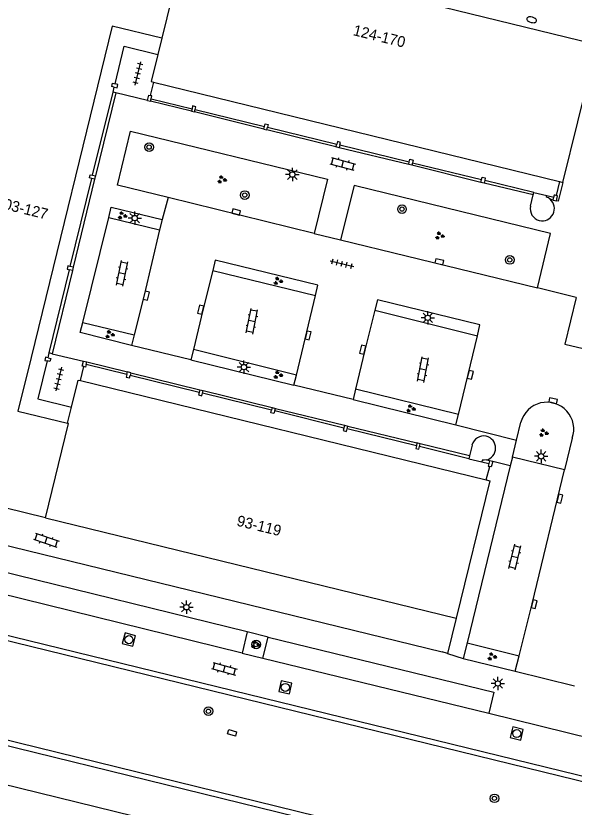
# Model space of a CAD drawing. Extents: x 125000 to 129004, y 397500 to 399008.
# Drawn here: x 126192.5 to 126244.2, y 398305.6 to 398378.8 of the extents above; entities that cross this region are included whole.
import ezdxf

# ---------------------------------------------------------------- set-up
doc = ezdxf.new("R2010")
doc.units = 0
for name, color, linetype in [('gg-afsc-hekwerk', 7, 'Continuous'), ('gg-anno-huisnummerreeks BGT', 7, 'Continuous'), ('gg-bbg-hoofdgebouw', 7, 'Continuous'), ('gg-bbg-onder overbouw', 7, 'Continuous'), ('gg-bbg-pand overbouw', 7, 'Continuous'), ('gg-bbg-pilaar onder overbouw', 7, 'Continuous'), ('gg-bbg-pilaar pand', 7, 'Continuous'), ('gg-bbg-toegangstrap', 7, 'Continuous'), ('gg-bbg-tussenscheiding', 7, 'Continuous'), ('gg-knt-verharding', 7, 'Continuous'), ('gg-knt-verharding nz', 7, 'Continuous'), ('gt-grn-weggrens', 7, 'Continuous'), ('gt-symb-boom', 7, 'Continuous'), ('gt-symb-brandkraan', 7, 'Continuous'), ('gt-symb-groenvak', 7, 'Continuous'), ('gt-symb-klinker verharding', 7, 'Continuous'), ('gt-symb-kolk', 7, 'Continuous'), ('gt-symb-kolk center center', 7, 'Continuous'), ('gt-symb-lichtmast', 7, 'Continuous'), ('gt-symb-rioolschacht', 7, 'Continuous'), ('gt-symb-tegel verharding', 7, 'Continuous')]:
    doc.layers.add(name, color=color, linetype=linetype)

# ---------------------------------------------------------------- blocks, each defined once
blk = doc.blocks.new('gt0-GRVAK')
at = {"layer": 'gt-symb-groenvak'}
for p, q in [((-0.11, 0.189), (-0.228, 0.24)), ((-0.182, 0.153), (0.088, 0.153)), ((-0.091, 0.211), (-0.156, 0.322)), ((-0.047, 0.214), (-0.047, 0.393)), ((-0.004, 0.211), (0.061, 0.322)), ((0.015, 0.189), (0.133, 0.24)), ((0.262, -0.052), (0.197, 0.059)), ((0.305, -0.049), (0.305, 0.13)), ((0.349, -0.052), (0.414, 0.059)), ((-0.245, -0.228), (-0.363, -0.177)), ((-0.318, -0.264), (-0.047, -0.264)), ((-0.226, -0.206), (-0.291, -0.095)), ((-0.183, -0.203), (-0.183, -0.024)), ((-0.139, -0.206), (-0.074, -0.095)), ((-0.12, -0.228), (-0.002, -0.177)), ((0.243, -0.074), (0.125, -0.023)), ((0.17, -0.11), (0.441, -0.11)), ((0.368, -0.074), (0.486, -0.023))]:
    blk.add_line(p, q, dxfattribs=at)
blk = doc.blocks.new('gt0-BOOM')
at = {"layer": 'gt-symb-boom'}
for radius in [0.4, 0.2]:
    blk.add_circle((0, 0), radius, dxfattribs=at)
blk = doc.blocks.new('gt0-TEG1')
at = {"layer": 'gt-symb-tegel verharding'}
for p, q in [((-1.125, 0), (1.125, 0)), ((-0.9, -0.25), (-0.9, 0.25)), ((-0.45, -0.25), (-0.45, 0.25)), ((0, -0.25), (0, 0.25)), ((0.45, -0.25), (0.45, 0.25)), ((0.9, -0.25), (0.9, 0.25))]:
    blk.add_line(p, q, dxfattribs=at)
blk = doc.blocks.new('gt0-KOLK')
at = {"layer": 'gt-symb-kolk'}
blk.add_lwpolyline([(0, 0), (0.375, 0), (0.375, 0.4), (-0.375, 0.4), (-0.375, 0), (0, 0)], dxfattribs=at)
blk = doc.blocks.new('gt0-KL1')
at = {"layer": 'gt-symb-klinker verharding'}
for p, q in [((-1.15, 0.3), (1.15, 0.3)), ((-1, -0.3), (-1, 0.3)), ((-0.5, 0.3), (-0.5, 0.45)), ((0, -0.3), (0, 0.3)), ((0.5, 0.3), (0.5, 0.45)), ((1, -0.3), (1, 0.3)), ((-1.15, -0.3), (1.15, -0.3)), ((-0.5, -0.45), (-0.5, -0.3)), ((0.5, -0.45), (0.5, -0.3))]:
    blk.add_line(p, q, dxfattribs=at)
blk = doc.blocks.new('gt0-LMAST')
at = {"layer": 'gt-symb-lichtmast'}
for p, q in [((-0.182, 0.173), (-0.447, 0.438)), ((-0.005, 0.246), (-0.005, 0.621)), ((0.172, 0.173), (0.437, 0.438)), ((-0.255, -0.004), (-0.63, -0.004)), ((-0.182, -0.181), (-0.447, -0.446)), ((-0.005, -0.254), (-0.005, -0.629)), ((0.437, -0.446), (0.172, -0.181)), ((0.245, -0.004), (0.62, -0.004))]:
    blk.add_line(p, q, dxfattribs=at)
blk.add_circle((-0.005, -0.004), 0.25, dxfattribs=at)
blk = doc.blocks.new('gt0-BR')
at = {"layer": 'gt-symb-brandkraan'}
for centre, radius, start, end in [((-0.244, 0), 0.206, 107.56694, 252.43307), ((0.599, -2.664), 3, 106.89205, 107.56694), ((0, -0.691), 0.938, 73.10799, 106.89205), ((-0.599, -2.664), 3, 72.43309, 73.10799), ((0.244, 0), 0.206, 287.56695, 72.43309), ((0.599, 2.664), 3, 252.43307, 253.10797), ((0, 0.691), 0.938, 253.10797, 286.89206), ((-0.599, 2.664), 3, 286.89206, 287.56695)]:
    blk.add_arc(centre, radius, start, end, dxfattribs=at)
blk = doc.blocks.new('gt0-RS')
at = {"layer": 'gt-symb-rioolschacht'}
blk.add_lwpolyline([(-0.5, -0.5), (0.5, -0.5), (0.5, 0.5), (-0.5, 0.5)], close=True, dxfattribs=at)
blk.add_circle((0, 0), 0.375, dxfattribs=at)
blk = doc.blocks.new('gt0-KOLKCC')
at = {"layer": 'gt-symb-kolk center center'}
blk.add_lwpolyline([(-0.375, 0.2), (0.375, 0.2), (0.375, -0.2), (-0.375, -0.2)], close=True, dxfattribs=at)

msp = doc.modelspace()

# ---------------------------------------------------------------- linework, layer by layer
at = {"layer": 'gg-afsc-hekwerk'}
msp.add_lwpolyline([(126244.357, 398352.716), (126243.311, 398348.418), (126251.423, 398346.504)], dxfattribs=at)
at = {"layer": 'gg-bbg-hoofdgebouw'}
for p, q in [((126246.254, 398376.097), (126208.148, 398385.442)), ((126243.134, 398363.374), (126246.254, 398376.097)), ((126242.819, 398363.451), (126243.134, 398363.374)), ((126195.241, 398332.331), (126233.242, 398323.04))]:
    msp.add_line(p, q, dxfattribs=at)
for points in [[(126205.642, 398375.197), (126205.032, 398372.706), (126205.222, 398372.66)], [(126197.644, 398342.572), (126198.26, 398345.089), (126198.466, 398345.039)], [(126195.241, 398332.331), (126185.923, 398334.609), (126180.109, 398336.023), (126180.125, 398336.091), (126179.162, 398336.334), (126179.386, 398337.301), (126179.318, 398337.318)], [(126236.04, 398335.842), (126236.354, 398335.765), (126233.242, 398323.04)]]:
    msp.add_lwpolyline(points, dxfattribs=at)
at = {"layer": 'gg-bbg-onder overbouw'}
for p, q in [((126206.014, 398376.717), (126205.642, 398375.197)), ((126205.222, 398372.66), (126242.819, 398363.451)), ((126198.466, 398345.039), (126236.04, 398335.842)), ((126197.28, 398341.087), (126197.644, 398342.572))]:
    msp.add_line(p, q, dxfattribs=at)
msp.add_lwpolyline([(126206.014, 398376.717), (126201.415, 398377.841), (126193.901, 398347.169), (126192.686, 398342.212), (126197.28, 398341.087)], dxfattribs=at)
at = {"layer": 'gg-bbg-pand overbouw'}
for p, q in [((126201.486, 398371.715), (126201.601, 398372.188)), ((126205.222, 398372.66), (126204.941, 398371.417)), ((126199.603, 398364.029), (126201.486, 398371.715)), ((126205.019, 398371.12), (126208.8, 398370.194)), ((126209.089, 398370.123), (126215.507, 398368.552)), ((126215.798, 398368.48), (126222.197, 398366.914)), ((126222.488, 398366.842), (126228.914, 398365.269)), ((126229.206, 398365.197), (126235.604, 398363.631)), ((126197.536, 398355.588), (126199.531, 398363.736)), ((126240.45, 398362.444), (126235.895, 398363.56)), ((126242.819, 398363.451), (126242.514, 398362.171)), ((126240.45, 398362.444), (126241.635, 398362.158)), ((126241.635, 398362.158), (126242.302, 398361.997)), ((126195.578, 398347.591), (126197.465, 398355.296)), ((126195.469, 398347.145), (126195.578, 398347.591)), ((126202.764, 398345.593), (126198.991, 398346.521)), ((126198.466, 398345.039), (126198.772, 398346.324)), ((126209.472, 398343.942), (126203.061, 398345.52)), ((126216.162, 398342.297), (126209.765, 398343.871)), ((126222.865, 398340.648), (126216.459, 398342.224)), ((126229.568, 398338.999), (126223.157, 398340.576)), ((126234.428, 398337.803), (126229.858, 398338.927)), ((126234.428, 398337.803), (126235.616, 398337.528)), ((126235.616, 398337.528), (126236.283, 398337.374)), ((126236.04, 398335.842), (126236.366, 398337.084))]:
    msp.add_line(p, q, dxfattribs=at)
for points in [[(126201.673, 398372.482), (126202.529, 398375.979), (126205.642, 398375.197)], [(126195.397, 398346.85), (126194.54, 398343.35), (126197.644, 398342.572)]]:
    msp.add_lwpolyline(points, dxfattribs=at)
at = {"layer": 'gg-bbg-pilaar onder overbouw'}
for p in [(126242.302, 398361.997), (126242.514, 398362.171)]:
    msp.add_line(p, (126242.354, 398362.21), dxfattribs=at)
for points in [[(126201.601, 398372.188), (126201.366, 398372.251), (126201.444, 398372.541), (126201.673, 398372.482)], [(126205.019, 398371.12), (126205.086, 398371.379), (126204.941, 398371.417)], [(126209.089, 398370.123), (126209.15, 398370.377), (126208.858, 398370.447), (126208.8, 398370.194)], [(126215.507, 398368.552), (126215.567, 398368.789), (126215.858, 398368.716), (126215.798, 398368.48)], [(126222.488, 398366.842), (126222.551, 398367.066), (126222.262, 398367.147), (126222.197, 398366.914)], [(126228.914, 398365.269), (126228.97, 398365.508), (126229.262, 398365.44), (126229.206, 398365.197)], [(126199.531, 398363.736), (126199.305, 398363.792), (126199.377, 398364.084), (126199.603, 398364.029)], [(126235.604, 398363.631), (126235.655, 398363.864), (126235.948, 398363.799), (126235.895, 398363.56)], [(126197.536, 398355.588), (126197.316, 398355.642), (126197.244, 398355.35), (126197.465, 398355.296)], [(126195.469, 398347.145), (126195.237, 398347.199), (126195.168, 398346.907), (126195.397, 398346.85)], [(126198.991, 398346.521), (126198.931, 398346.286), (126198.772, 398346.324)], [(126202.764, 398345.593), (126202.708, 398345.361), (126202.998, 398345.284), (126203.061, 398345.52)], [(126209.472, 398343.942), (126209.413, 398343.704), (126209.704, 398343.632), (126209.765, 398343.871)], [(126216.459, 398342.224), (126216.386, 398341.975), (126216.096, 398342.053), (126216.162, 398342.297)], [(126222.865, 398340.648), (126222.805, 398340.409), (126223.096, 398340.337), (126223.157, 398340.576)], [(126229.568, 398338.999), (126229.516, 398338.763), (126229.809, 398338.699), (126229.858, 398338.927)], [(126236.283, 398337.374), (126236.217, 398337.124), (126236.366, 398337.084)]]:
    msp.add_lwpolyline(points, dxfattribs=at)
at = {"layer": 'gg-bbg-pilaar pand'}
for p, q in [((126204.666, 398370.952), (126204.956, 398370.877)), ((126204.956, 398370.877), (126205.019, 398371.12)), ((126208.8, 398370.194), (126208.745, 398369.956)), ((126208.745, 398369.956), (126209.035, 398369.896)), ((126209.035, 398369.896), (126209.089, 398370.123)), ((126215.445, 398368.307), (126215.507, 398368.552)), ((126215.736, 398368.233), (126215.798, 398368.48)), ((126215.445, 398368.307), (126215.736, 398368.233)), ((126222.126, 398366.661), (126222.197, 398366.914)), ((126222.416, 398366.585), (126222.126, 398366.661)), ((126222.488, 398366.842), (126222.416, 398366.585)), ((126228.856, 398365.023), (126228.914, 398365.269)), ((126229.15, 398364.956), (126228.856, 398365.023)), ((126229.206, 398365.197), (126229.15, 398364.956)), ((126199.784, 398363.674), (126199.531, 398363.736)), ((126199.603, 398364.029), (126199.853, 398363.968)), ((126199.853, 398363.968), (126199.784, 398363.674)), ((126235.548, 398363.379), (126235.604, 398363.631)), ((126235.839, 398363.31), (126235.548, 398363.379)), ((126235.895, 398363.56), (126235.839, 398363.31)), ((126242.24, 398361.744), (126242.302, 398361.997)), ((126242.646, 398362.138), (126242.514, 398362.171)), ((126242.532, 398361.672), (126242.646, 398362.138)), ((126242.24, 398361.744), (126242.532, 398361.672)), ((126197.723, 398355.232), (126197.465, 398355.296)), ((126197.792, 398355.526), (126197.536, 398355.588)), ((126197.792, 398355.526), (126197.723, 398355.232)), ((126198.742, 398346.846), (126199.055, 398346.771)), ((126198.991, 398346.521), (126199.055, 398346.771)), ((126202.764, 398345.593), (126202.826, 398345.846)), ((126203.126, 398345.767), (126202.826, 398345.846)), ((126203.126, 398345.767), (126203.061, 398345.52)), ((126209.535, 398344.194), (126209.472, 398343.942)), ((126209.535, 398344.194), (126209.828, 398344.121)), ((126209.765, 398343.871), (126209.828, 398344.121)), ((126216.227, 398342.536), (126216.162, 398342.297)), ((126216.227, 398342.536), (126216.526, 398342.455)), ((126216.459, 398342.224), (126216.526, 398342.455)), ((126222.927, 398340.899), (126222.865, 398340.648)), ((126222.927, 398340.899), (126223.22, 398340.826)), ((126223.157, 398340.576), (126223.22, 398340.826)), ((126229.625, 398339.261), (126229.568, 398338.999)), ((126229.913, 398339.187), (126229.625, 398339.261)), ((126229.858, 398338.927), (126229.913, 398339.187)), ((126236.345, 398337.612), (126236.283, 398337.374)), ((126236.635, 398337.536), (126236.345, 398337.612))]:
    msp.add_line(p, q, dxfattribs=at)
for points in [[(126201.601, 398372.188), (126201.859, 398372.119), (126201.926, 398372.417), (126201.673, 398372.482)], [(126204.666, 398370.952), (126204.796, 398371.454), (126204.941, 398371.417)], [(126195.469, 398347.145), (126195.732, 398347.083), (126195.648, 398346.787), (126195.397, 398346.85)], [(126198.772, 398346.324), (126198.626, 398346.359), (126198.742, 398346.846)], [(126236.635, 398337.536), (126236.507, 398337.047), (126236.366, 398337.084)]]:
    msp.add_lwpolyline(points, dxfattribs=at)
at = {"layer": 'gg-bbg-toegangstrap'}
for p, q in [((126240.145, 398361.182), (126240.393, 398362.211)), ((126240.393, 398362.211), (126240.45, 398362.444)), ((126234.718, 398339.061), (126234.488, 398338.061)), ((126234.488, 398338.061), (126234.428, 398337.803))]:
    msp.add_line(p, q, dxfattribs=at)
for points in [[(126241.955, 398361.811), (126241.788, 398361.932), (126241.603, 398362.022), (126241.635, 398362.158)], [(126236.029, 398337.688), (126235.839, 398337.661), (126235.648, 398337.665), (126235.616, 398337.528)]]:
    msp.add_lwpolyline(points, dxfattribs=at)
for centre, radius, start, end in [((126241.219, 398360.917), 1.106, 166.15782, 255.75708), ((126241.202, 398360.956), 1.14, 257.07953, 48.63058), ((126235.833, 398338.754), 1.157, 79.75631, 164.58913), ((126235.77, 398338.791), 1.133, 283.22346, 76.25662)]:
    msp.add_arc(centre, radius, start, end, dxfattribs=at)
at = {"layer": 'gg-bbg-tussenscheiding'}
msp.add_line((126208.148, 398385.442), (126206.014, 398376.717), dxfattribs=at)
msp.add_lwpolyline([(126195.241, 398332.331), (126197.376, 398341.063), (126197.28, 398341.087)], dxfattribs=at)
at = {"layer": 'gg-knt-verharding'}
for p, q in [((126201.748, 398371.651), (126199.853, 398363.968)), ((126204.666, 398370.952), (126201.748, 398371.651)), ((126208.745, 398369.956), (126204.956, 398370.877)), ((126215.445, 398368.307), (126209.035, 398369.896)), ((126222.126, 398366.661), (126215.736, 398368.233)), ((126228.856, 398365.023), (126222.416, 398366.585)), ((126235.548, 398363.379), (126229.15, 398364.956)), ((126199.784, 398363.674), (126197.792, 398355.526)), ((126240.393, 398362.211), (126235.839, 398363.31)), ((126206.582, 398361.981), (126206.042, 398359.935)), ((126220.122, 398358.657), (126206.582, 398361.981)), ((126242.24, 398361.744), (126241.955, 398361.811)), ((126201.094, 398360.121), (126205.798, 398358.993)), ((126206.042, 398359.935), (126205.798, 398358.993)), ((126220.122, 398358.657), (126222.552, 398358.055)), ((126222.552, 398358.055), (126240.766, 398353.612)), ((126197.723, 398355.232), (126195.854, 398347.523)), ((126210.717, 398355.234), (126220.226, 398352.894)), ((126244.357, 398352.716), (126240.766, 398353.612)), ((126218.483, 398345.546), (126220.226, 398352.894)), ((126225.722, 398351.559), (126235.227, 398349.18)), ((126198.691, 398350.407), (126203.445, 398349.254)), ((126203.445, 398349.254), (126203.192, 398348.294)), ((126233.463, 398341.883), (126235.227, 398349.18)), ((126208.706, 398346.96), (126203.192, 398348.294)), ((126195.854, 398347.523), (126198.742, 398346.846)), ((126208.924, 398347.92), (126208.706, 398346.96)), ((126218.483, 398345.546), (126208.924, 398347.92)), ((126199.055, 398346.771), (126202.826, 398345.846)), ((126208.706, 398346.96), (126218.215, 398344.603)), ((126203.126, 398345.767), (126209.535, 398344.194)), ((126218.215, 398344.603), (126218.483, 398345.546)), ((126223.704, 398343.29), (126218.215, 398344.603)), ((126209.828, 398344.121), (126216.227, 398342.536)), ((126223.928, 398344.247), (126223.704, 398343.29)), ((126233.463, 398341.883), (126223.928, 398344.247)), ((126223.704, 398343.29), (126233.212, 398340.945)), ((126216.526, 398342.455), (126222.927, 398340.899)), ((126233.212, 398340.945), (126233.463, 398341.883)), ((126223.22, 398340.826), (126229.625, 398339.261)), ((126233.212, 398340.945), (126238.828, 398339.538)), ((126238.828, 398339.538), (126239.241, 398341.196)), ((126234.488, 398338.061), (126229.913, 398339.187)), ((126238.464, 398337.951), (126238.828, 398339.538)), ((126243.996, 398339.71), (126243.285, 398336.766)), ((126236.345, 398337.612), (126236.029, 398337.688)), ((126238.464, 398337.951), (126238.266, 398337.14)), ((126243.285, 398336.766), (126238.464, 398337.951)), ((126238.266, 398337.14), (126234.268, 398320.755)), ((126238.266, 398337.14), (126236.635, 398337.536)), ((126180.405, 398332.543), (126231.953, 398319.924)), ((126213.908, 398321.784), (126179.807, 398330.158)), ((126175.491, 398324.933), (126311.063, 398291.763)), ((126178.527, 398324.705), (126308.878, 398292.812)), ((126233.242, 398323.04), (126232.461, 398319.786)), ((126213.908, 398321.784), (126213.45, 398319.826)), ((126215.858, 398321.309), (126213.908, 398321.784)), ((126215.369, 398319.341), (126215.858, 398321.309)), ((126234.268, 398320.755), (126233.885, 398319.325)), ((126234.268, 398320.755), (126239.077, 398319.576)), ((126213.45, 398319.826), (126215.369, 398319.341)), ((126232.461, 398319.786), (126231.953, 398319.924)), ((126238.713, 398318.136), (126239.077, 398319.576)), ((126233.885, 398319.325), (126238.713, 398318.136)), ((126173.268, 398316.286), (126308.872, 398283.09)), ((126176.063, 398315.087), (126306.612, 398283.129)), ((126236.263, 398314.263), (126252.299, 398310.306))]:
    msp.add_line(p, q, dxfattribs=at)
for points in [[(126206.582, 398361.981), (126201.898, 398363.131), (126203.109, 398368.118), (126221.334, 398363.682), (126220.122, 398358.657)], [(126243.134, 398363.374), (126242.702, 398361.632), (126242.532, 398361.672)], [(126240.766, 398353.612), (126241.972, 398358.645), (126223.924, 398363.045), (126223.796, 398363.088), (126222.552, 398358.055)], [(126201.094, 398360.121), (126201.305, 398361.094), (126206.042, 398359.935)], [(126205.798, 398358.993), (126204.375, 398352.945), (126203.445, 398349.254)], [(126220.226, 398352.894), (126220.46, 398353.878), (126210.947, 398356.169), (126210.717, 398355.234)], [(126210.717, 398355.234), (126209.796, 398351.553), (126208.924, 398347.92)], [(126235.227, 398349.18), (126235.437, 398350.179), (126225.956, 398352.518), (126225.722, 398351.559)], [(126225.722, 398351.559), (126224.791, 398347.847), (126223.928, 398344.247)], [(126203.192, 398348.294), (126198.441, 398349.483), (126198.691, 398350.407)], [(126239.077, 398319.576), (126240.28, 398324.393), (126243.285, 398336.766)], [(126215.858, 398321.309), (126236.728, 398316.208), (126236.263, 398314.263)]]:
    msp.add_lwpolyline(points, dxfattribs=at)
msp.add_arc((126241.646, 398340.54), 2.493, 340.53821, 164.75237, dxfattribs=at)
at = {"layer": 'gg-knt-verharding nz'}
for p, q in [((126198.691, 398350.407), (126201.094, 398360.121)), ((126213.45, 398319.826), (126179.322, 398328.207)), ((126215.369, 398319.341), (126236.263, 398314.263)), ((126191.007, 398307.777), (126206.986, 398303.871))]:
    msp.add_line(p, q, dxfattribs=at)
at = {"layer": 'gt-grn-weggrens'}
for p, q in [((126201.748, 398371.651), (126201.486, 398371.715)), ((126195.854, 398347.523), (126195.578, 398347.591)), ((126232.461, 398319.786), (126233.885, 398319.325)), ((126238.713, 398318.136), (126244.214, 398316.806))]:
    msp.add_line(p, q, dxfattribs=at)

# ---------------------------------------------------------------- block references
at = {"layer": 'gt-symb-boom'}
for p in [(126204.826, 398366.636), (126213.677, 398362.203), (126228.238, 398360.902), (126238.207, 398356.195), (126214.735, 398320.606), (126210.313, 398314.439), (126236.795, 398306.382)]:
    msp.add_blockref('gt0-BOOM', p, dxfattribs=at)
at = {"layer": 'gt-symb-brandkraan', "rotation": -13.8834180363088}
msp.add_blockref('gt0-BR', (126240.244, 398378.419), dxfattribs=at)
at = {"layer": 'gt-symb-groenvak'}
for p in [(126211.556, 398363.632), (126202.332, 398360.298), (126231.707, 398358.437), (126216.749, 398354.249), (126201.17, 398349.306), (126216.749, 398345.564), (126229.033, 398342.443), (126241.331, 398340.203), (126214.654, 398320.618), (126236.558, 398319.494)]:
    msp.add_blockref('gt0-GRVAK', p, dxfattribs=at)
at = {"layer": 'gt-symb-klinker verharding'}
for p, rotation in [((126222.756, 398365.079), -14.77272395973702), ((126202.332, 398354.947), 78.75747429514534), ((126214.346, 398350.527), 78.75747429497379), ((126230.187, 398346.057), 78.7574742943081), ((126195.309, 398330.262), -18.779117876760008), ((126238.69, 398328.702), 76.35276166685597), ((126211.791, 398318.363), -15.66210634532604)]:
    msp.add_blockref('gt0-KL1', p, dxfattribs=dict(at, rotation=rotation))
at = {"layer": 'gt-symb-kolk'}
for p, rotation in [((126212.842, 398360.437), -13.716469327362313), ((126231.645, 398355.839), -13.702889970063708), ((126204.375, 398352.945), -103.24380202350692), ((126209.796, 398351.553), 75.93596328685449), ((126219.354, 398349.258), -103.1749266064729), ((126224.791, 398347.847), 75.93596328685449), ((126234.367, 398345.616), -103.59156043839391), ((126242.181, 398342.975), -12.41077472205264), ((126242.655, 398334.158), -103.64723833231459), ((126240.28, 398324.393), -104.00844348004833)]:
    msp.add_blockref('gt0-KOLK', p, dxfattribs=dict(at, rotation=rotation))
at = {"layer": 'gt-symb-kolk center center', "rotation": -16.49622422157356}
msp.add_blockref('gt0-KOLKCC', (126212.512, 398312.442), dxfattribs=at)
at = {"layer": 'gt-symb-lichtmast'}
for p in [(126218.095, 398364.103), (126203.505, 398360.073), (126230.63, 398350.846), (126213.608, 398346.286), (126241.123, 398338.032), (126208.288, 398324.071), (126237.114, 398317.012)]:
    msp.add_blockref('gt0-LMAST', p, dxfattribs=at)
at = {"layer": 'gt-symb-rioolschacht'}
for p, rotation in [((126202.959, 398321.068), -15.37072543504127), ((126217.438, 398316.646), -12.410774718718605), ((126238.861, 398312.378), -13.952823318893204)]:
    msp.add_blockref('gt0-RS', p, dxfattribs=dict(at, rotation=rotation))
at = {"layer": 'gt-symb-tegel verharding'}
for p, rotation in [((126203.797, 398373.45), 76.22785456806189), ((126222.676, 398355.855), -13.827795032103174), ((126196.459, 398345.181), -103.77214543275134)]:
    msp.add_blockref('gt0-TEG1', p, dxfattribs=dict(at, rotation=rotation))

# ---------------------------------------------------------------- texts
at = {"layer": 'gg-anno-huisnummerreeks BGT'}
for s, rotation, p in [('124-170', 346.2, (126223.641, 398377.009)), ('103-127', 346.2, (126190.557, 398361.103)), ('93-119', 346.3, (126212.874, 398331.621))]:
    msp.add_text(s, height=1, rotation=rotation, dxfattribs=at).set_placement(p)

doc.saveas('drawing.dxf')
